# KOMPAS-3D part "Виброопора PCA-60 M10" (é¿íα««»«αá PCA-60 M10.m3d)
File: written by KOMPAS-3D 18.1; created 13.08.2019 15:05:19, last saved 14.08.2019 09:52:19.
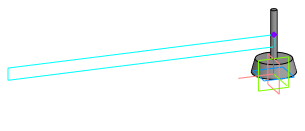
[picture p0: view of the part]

Document properties: Автор: Пользователь Windows; Полное имя файла: D:\Мембранные насосы\Мембранный электропривод\А302-00.00.000 - ASTRA-302 (МЭ200)\3Д ПВХ\Виброопора PCA-60 M10.m3d

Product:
- Part/product: Виброопора PCA-60 M10
    Масса: 0.60876

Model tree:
1. Точка:1  (with: Элемент выдавливания:1)  (labels: Каркас\Подставка 2; Виброопора PCA-60 M10)
     Y = 1.5; Z = 65
2. Параллельная плоскость:1  (with: Элемент выдавливания:1)  (labels: Каркас\Подставка 1; Виброопора PCA-60 M10)
3. Эскиз:3
4. Элемент вращения:2  (with: Элемент выдавливания:1)  (labels: Подставка 2; Виброопора PCA-60 M10)
     Угол 1 = 360

Referenced files in D:\Мембранные насосы\Мембранный электропривод\А302-00.00.000 - ASTRA-302 (МЭ200)\3Д ПВХ\: А302-01.00.000  - Мембранный насос ASTRA-302 ПВХ.a3d, А302-01.40.000 - Каркас.a3d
